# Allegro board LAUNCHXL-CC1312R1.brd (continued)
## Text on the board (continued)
User.27: FIGURE | FINISHED_SIZE | 0.2 | 0.201 | 0.6 | 1.05 | 1.1 | 3.2 | 0.899 | 1.0 | 1.3x0.6 | DRILL CHART: TOP to BOTTOM | ALL UNITS ARE IN MILLIMETERS | ROTATION | - | 90.000 | PLATED | NON-PLATED | QTY | 1076 | 25 | 15 | 75 | 1 | 4 | 6 | 3 | 2 | 1209 | TOTAL HOLES:
